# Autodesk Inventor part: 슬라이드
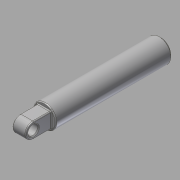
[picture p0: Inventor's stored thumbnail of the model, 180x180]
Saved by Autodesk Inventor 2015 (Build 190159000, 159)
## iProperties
Created: 2016-02
Part Number: 슬라이드
Material: 강철, 연강
Document SubType Name: Modeling
Designer: test
Density: 1 g/cm^3
Appearance: 강철
Author: test
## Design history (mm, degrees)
sketch "스케치2"
  geometry: C1 r 6 at (0, 0); 1 further point
  constraints: 1 centre point, 1 coincident
  dimensions: "d0" = 12 diameter of C1
extrude "돌출1" new body sketch "스케치2" distance "d1" = 60; taper "d2" = 0 deg
hole "구멍1" diameter "d5" = 5.917; stored, may be unused: countersink angle "d9" = 90 deg, drill point angle "d11" = 118 deg; dims "d3" = 10, "d4" = 10, "d6" = 10, "d7" = 4, "d8" = 2, "d10" = 12
chamfer "모따기1" distance "d12" = 1; stored, may be unused: second distance "d13" = 2, angle "d14" = 45 deg
sketch "스케치3"
  geometry: L1 (0, 6)-(0, -6) reference; L2 (0, 4)-(-9, 4); L3 (-9, -4)-(0, -4); L4 (0, -4)-(0, 4); C1 r 2.5 at (-9, 0); A1 r 4 centre (-9, 0) between (-9, 4) and (-9, -4); 2 further points
  constraints: 6 end point, 2 centre point, 2 point on circle, 2 tangent, 1 coincident, 1 horizontal, 1 horizontal alignment, 1 midpoint, 1 parallel, 1 point on line, 1 vertical
  dimensions: "d15" = 13 dimension on A1 L1; "d16" = 8 distance between parallel lines of L3 L2; "d17" = 5 diameter of C1
extrude "돌출2" join sketch "스케치3" stored distance "d18" = 7; taper "d19" = 0 deg
chamfer "모따기2" distance "d20" = 0.5; stored, may be unused: second distance "d21" = 2, angle "d22" = 45 deg
fillet "모깎기1" dims "d23" = 0.5
fillet "모깎기2" dims "d24" = 0.5
fillet "모깎기3" dims "d25" = 0.5
node "솔리드1"
